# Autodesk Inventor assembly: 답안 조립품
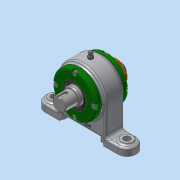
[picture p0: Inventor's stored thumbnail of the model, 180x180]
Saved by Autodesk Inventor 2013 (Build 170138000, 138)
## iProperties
Created: 2019-05
Part Number: 답안 조립품
Document SubType Name: Assembly
Designer: dgall
Author: dgall
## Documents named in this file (13)
- C:\Users\dgall\Desktop\490504V1052\답안 조립품.iam
- C:\Users\dgall\Desktop\490504V1052\본체.ipt
- C:\Users\dgall\Desktop\490504V1052\축.ipt
- C:\Users\dgall\Desktop\490504V1052\오일 실 28 40 5 B.ipt
- C:\Users\dgall\Desktop\490504V1052\앵귤러 볼 베어링 7205.ipt
- C:\Users\dgall\Desktop\490504V1052\개스킷.ipt
- C:\Users\dgall\Desktop\490504V1052\커버.ipt
- C:\Users\dgall\Desktop\490504V1052\칼라.ipt
- C:\Users\dgall\Desktop\490504V1052\베어링너트.ipt
- C:\Users\dgall\Desktop\490504V1052\그리스니플개스킷.ipt
- C:\Users\dgall\Desktop\490504V1052\그리스니플 M6.ipt
- 그리스니플  M6.ipt
- C:\Users\dgall\Desktop\490504V1052\볼트 M4.ipt
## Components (4 placed, 3 different names)
1. 개스킷:1
2. 개스킷:2
3. 그리스니플개스킷:1
4. 그리스니플  M6:1 — 각도:1, 각도:2
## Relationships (2: Angle 2)
- 각도:1 [Angle]: 그리스니플  M6:1
- 각도:2 [Angle]: 그리스니플  M6:1
